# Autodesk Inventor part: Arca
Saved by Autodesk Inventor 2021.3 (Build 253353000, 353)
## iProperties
Created: 2022-09
Part Number: Arca
Material: Generic
Document SubType Name: Modeling
Designer: Administrator
Density: 1 g/cm^3
Appearance: Default
Title: Arca v2
Author: Administrator
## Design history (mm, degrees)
feature "Arca" [Body]
feature "Socket Body" [Body]
feature "Shade Ring" [Body]
feature "Shade Ring +Collar" [Body]
feature "Socket" [Body]
feature "Body1"
feature "Metal Strain Relief" [Body]
feature "Fabric Cord (1)" [Body]
feature "Stem (Threaded)" [Body]
feature "Cap (Threaded)" [Body]
feature "5M Set Screw" [Body]
feature "G30-Bulb" [Body]
body "Solid1"
body "Solid2"
body "Solid3"
body "Solid4"
body "Solid5"
body "Solid6"
body "Solid7"
body "Solid8"
body "Solid9"
body "Solid10"
body "Solid11"
body "Solid12"
